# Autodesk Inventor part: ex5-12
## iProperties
Shininess: 64.0
Length Units: 11269
Angle Units: 11279
Time Units: 11290
Mass Units: 11283
Length Display Precision: 3
Angle Display Precision: 2
Compacted: True
Part Number: ex5-12
Document SubType Name: Modeling
Created: 2003-11
Cost Center: 0 kg
Designer: Elise Moss
Authority: 11346.17 mm^3
Manufacturer: Standard
Standards Organization: Custom
Density: 0.0
Volumn: 0.0
Area: 0.0
PropertySet Name: Model Information
Control State: 0
Master: False
Checked Out: False
SaveDate: 2003-11-24
SaveTime: 12:18
TotalMass: 0 kg
TotalVolume: 11346.17 mm^3
Author: Elise Moss
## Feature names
1. Extrusion1
2. Hole1
3. Shell3
4. Chamfer1
